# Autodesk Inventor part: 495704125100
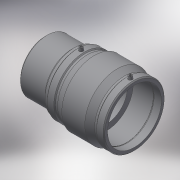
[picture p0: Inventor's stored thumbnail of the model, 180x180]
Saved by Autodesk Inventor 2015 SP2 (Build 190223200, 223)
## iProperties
Created: 2017-06
Part Number: 495704125100
Material: Generic
Description: PLASSON PE CAST IRON SPIGOT COUPLER TRANSITION 125-100
Document SubType Name: Modeling
Designer: KIM
Mass: 55.0731 g
Surface Area: 148.067 cm^2
Volume: 55.0731 cm^3
Density: 1 g/cm^3
Appearance: Default
Author: KIM
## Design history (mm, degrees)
derived "495704.ipt"
feature "Solid1::495704.ipt"
tag "TaggingFeature1"
body "Solid1"
other parameters: "d13" = 173, "d14" = 17.6296, "d15" = 85, "d16" = 85, "d17" = 118.75, "d18" = 125, "d19" = 3.52592, "d20" = 168 deg, "d22" = 147.58, "d23" = 157, "d24" = 143.1526, "d25" = 135 deg, "d26" = 69.2, "d27" = 135 deg, "d29" = 87, "d35" = 15, "d39" = 5 deg, "d45" = 4, "d46" = 14, "d47" = 0, "d50" = 3, "d51" = 0, "d52" = 24.65, "d53" = 6.1625, "d54" = 118, "d55" = 0.1, "d56" = 129.8, "d57" = 91, "d58" = 107, "d60" = 98, "d62" = 3.54, "d65" = 5.9, "d_" = 125, "L_1" = 85, "D_1" = 157, "A_" = 87, "d_2" = 12, "L_2" = 107, "H_" = 91, "D_" = 118, "d_1" = 98
